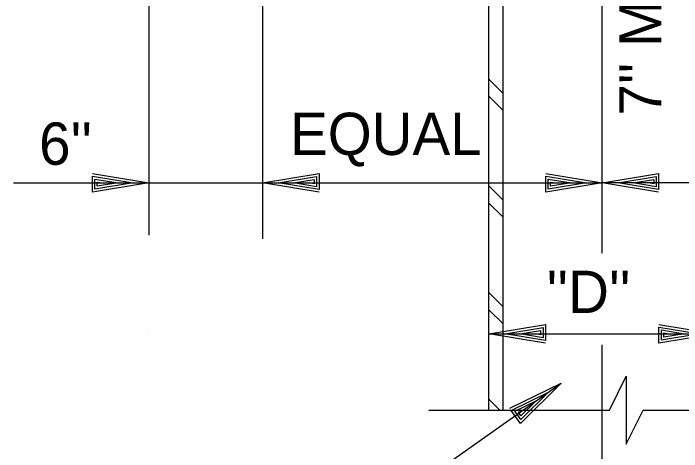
# Model space of a CAD drawing. Extents: x 22411.4 to 22495.4, y 22369.6 to 22415.
# Drawn here: x 22466.74 to 22469.692, y 22384.525 to 22386.462 of the extents above; entities that cross this region are included whole.
import ezdxf

# ---------------------------------------------------------------- set-up
doc = ezdxf.new("R2010")
doc.units = 0
for name, color, linetype in [('Level 1', 7, 'Continuous'), ('Level 2', 7, 'Continuous'), ('Level 4', 7, 'Continuous'), ('Level 8', 7, 'Continuous')]:
    doc.layers.add(name, color=color, linetype=linetype)

msp = doc.modelspace()

# ---------------------------------------------------------------- linework, layer by layer
at = {"layer": 'Level 1'}
for p, q in [((22469.3408, 22385.4019), (22469.3408, 22394.6266)), ((22467.3386, 22388.261), (22467.3386, 22385.4818)), ((22467.8408, 22387.4555), (22467.8408, 22385.4646)), ((22466.7401, 22385.7124), (22467.3386, 22385.7124)), ((22467.3386, 22385.7124), (22467.8408, 22385.7124)), ((22467.8408, 22385.7124), (22467.8408, 22385.7124)), ((22467.8408, 22385.7124), (22469.3408, 22385.7124)), ((22467.9102, 22385.7124), (22467.9102, 22385.7124)), ((22469.2715, 22385.7124), (22469.2715, 22385.7124)), ((22469.3408, 22385.7124), (22469.3408, 22385.7124)), ((22469.3408, 22385.7124), (22469.3408, 22385.7124)), ((22470.8408, 22385.7124), (22469.3408, 22385.7124)), ((22469.4102, 22385.7124), (22469.4102, 22385.7124)), ((22467.3386, 22385.0457), (22467.3386, 22385.0457)), ((22468.8408, 22385.0457), (22469.8408, 22385.0457)), ((22469.2715, 22385.0457), (22469.2715, 22385.0457)), ((22469.3408, 22385.0457), (22469.3408, 22385.0457)), ((22469.3408, 22385.0457), (22469.3408, 22385.0457)), ((22469.4102, 22385.0457), (22469.4102, 22385.0457)), ((22469.3408, 22384.2027), (22469.3408, 22384.9966)), ((22469.16, 22384.8274), (22469.16, 22384.8274)), ((22469.1034, 22384.7873), (22469.1034, 22384.7873)), ((22468.5748, 22384.708), (22469.3728, 22384.708)), ((22469.5223, 22384.708), (22470.1021, 22384.708))]:
    msp.add_line(p, q, dxfattribs=at)
msp.add_lwpolyline([(22469.3728, 22384.708), (22469.4473, 22384.858), (22469.4473, 22384.5583), (22469.5223, 22384.708)], dxfattribs=at)
at = {"layer": 'Level 2'}
for p, q in [((22468.8408, 22384.708), (22468.8408, 22387.6934)), ((22468.9033, 22384.708), (22468.9033, 22387.6934))]:
    msp.add_line(p, q, dxfattribs=at)
for points in [[(22467.0893, 22385.7537), (22467.3386, 22385.7124), (22467.0893, 22385.6711), (22467.0893, 22385.7417), (22467.2693, 22385.7124), (22467.0999, 22385.6844), (22467.0999, 22385.7297), (22467.2026, 22385.7124), (22467.1106, 22385.6977), (22467.1106, 22385.7164), (22467.1333, 22385.7124)], [(22468.0902, 22385.6711), (22467.8408, 22385.7124), (22468.0902, 22385.7537), (22468.0902, 22385.6831), (22467.9102, 22385.7124), (22468.0795, 22385.7404), (22468.0795, 22385.6951), (22467.9768, 22385.7124), (22468.0688, 22385.7271), (22468.0688, 22385.7084), (22468.0462, 22385.7124)], [(22469.0915, 22385.7537), (22469.3408, 22385.7124), (22469.0915, 22385.6711), (22469.0915, 22385.7417), (22469.2715, 22385.7124), (22469.1022, 22385.6844), (22469.1022, 22385.7297), (22469.2048, 22385.7124), (22469.1128, 22385.6977), (22469.1128, 22385.7164), (22469.1355, 22385.7124)], [(22469.5902, 22385.6711), (22469.3408, 22385.7124), (22469.5902, 22385.7537), (22469.5902, 22385.6831), (22469.4102, 22385.7124), (22469.5795, 22385.7404), (22469.5795, 22385.6951), (22469.4768, 22385.7124), (22469.5688, 22385.7271), (22469.5688, 22385.7084), (22469.5462, 22385.7124)], [(22469.0902, 22385.0044), (22468.8408, 22385.0457), (22469.0902, 22385.0871), (22469.0902, 22385.0164), (22468.9102, 22385.0457), (22469.0795, 22385.0737), (22469.0795, 22385.0284), (22468.9768, 22385.0457), (22469.0688, 22385.0604), (22469.0688, 22385.0417), (22469.0462, 22385.0457)], [(22469.5915, 22385.0871), (22469.8408, 22385.0457), (22469.5915, 22385.0044), (22469.5915, 22385.0751), (22469.7715, 22385.0457), (22469.6022, 22385.0177), (22469.6022, 22385.0631), (22469.7048, 22385.0457), (22469.6128, 22385.0311), (22469.6128, 22385.0497), (22469.6355, 22385.0457)], [(22467.8945, 22384.1587), (22468.215, 22384.1587), (22469.16, 22384.8274)], [(22468.9326, 22384.7171), (22469.16, 22384.8274), (22468.9803, 22384.6496), (22468.9395, 22384.7073), (22469.1034, 22384.7873), (22468.9813, 22384.6666), (22468.9551, 22384.7037), (22469.049, 22384.7488), (22468.9823, 22384.6837), (22468.9716, 22384.6989), (22468.9924, 22384.7088)]]:
    msp.add_lwpolyline(points, dxfattribs=at)
at = {"layer": 'Level 8'}
for p, q in [((22467.2693, 22385.7124), (22467.2693, 22385.7124)), ((22467.3386, 22385.7124), (22467.3386, 22385.7124)), ((22467.8408, 22385.7124), (22467.8408, 22385.7124)), ((22467.9102, 22385.7124), (22467.9102, 22385.7124)), ((22469.2715, 22385.7124), (22469.2715, 22385.7124)), ((22469.3408, 22385.7124), (22469.3408, 22385.7124)), ((22469.3408, 22385.7124), (22469.3408, 22385.7124)), ((22469.4102, 22385.7124), (22469.4102, 22385.7124)), ((22468.8408, 22385.0457), (22468.8408, 22385.0457)), ((22468.9102, 22385.0457), (22468.9102, 22385.0457))]:
    msp.add_line(p, q, dxfattribs=at)
for points in [[(22468.9033, 22386.108), (22468.8408, 22386.1705)], [(22468.9033, 22386.0326), (22468.8408, 22386.0951)], [(22468.9033, 22385.6366), (22468.8408, 22385.6991)], [(22468.9033, 22385.5612), (22468.8408, 22385.6236)], [(22468.9033, 22385.1652), (22468.8408, 22385.2277)], [(22468.9033, 22385.0898), (22468.8408, 22385.1522)], [(22468.8891, 22384.708), (22468.8408, 22384.7563)]]:
    msp.add_lwpolyline(points, dxfattribs=at)

# ---------------------------------------------------------------- texts
at = {"layer": 'Level 4'}
msp.add_text("7'' MIN CL", height=0.18667, rotation=90, dxfattribs=at).set_placement((22469.6026, 22386.0098))
for s, p in [('EQUAL', (22467.9622, 22385.8358)), ("6''", (22466.8538, 22385.7928)), ("''D''", (22469.0952, 22385.1378))]:
    msp.add_text(s, height=0.18667, dxfattribs=at).set_placement(p)

doc.saveas('drawing.dxf')
